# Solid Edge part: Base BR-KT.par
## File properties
Last saved by: nakano
Revision: 76
Density: 1011.76138724735 kg/m^3
Accuracy: 0.990
Material: AL5D plastic
Face Style: Black (dull)
Fill Style: Normal
Virtual Style: Normal
Grouping: Non-metals
LibraryName: Materials-GOST
Coef. of Thermal Exp: 0.0
Thermal Conductivity: 0.0
Specific Heat: 0.0
Modulus of Elasticity: 0.0
Poisson's Ratio: 0.33
Yield Stress: 0.0
Ultimate Stress: 0.0
Elongation: 0.0
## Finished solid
Body 1: solid body, 387 faces, 785 edges, 404 vertices.
  Faces by surface: cylinder 159, plane 89, blend 76, torus 41, sphere 20, cone 2
  Edges by curve: circle 333, line 292, intersection 120, ellipse 40
Bounding box of the edges (mm; curved faces can reach further): 99.568 x 42.316 x 99.568, from (-49.784, 0, -49.784) to (49.784, 42.3164, 49.784).
Cylindrical faces by radius (mm): R0.0254 x70, R0.254 x50, R1.1811 x4, R1.5875 x8, R1.778 x8, R2.1463 x4, R3.175 x5, R3.3655 x4, R4.7625 x5, R9.525 x1
Conical faces (half-angle, radius in mm at the cone's reference point): 4 deg R44.2911 x1, 4 deg R46.8249 x1
Toroidal faces (ring radius, tube radius in mm): R1.524 r0.254 x8, R1.8415 r0.254 x8, R3.2004 r0.0254 x10, R3.429 r0.254 x10, R46.3512 r0.508 x1, R49.8432 r0.254 x4
Spherical faces by radius (mm): R0.0254 x20
Planar faces by outward normal: +x 2, +y 20, +z 1, -x 2, -y 19, -z 1, oblique 44
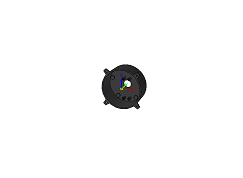
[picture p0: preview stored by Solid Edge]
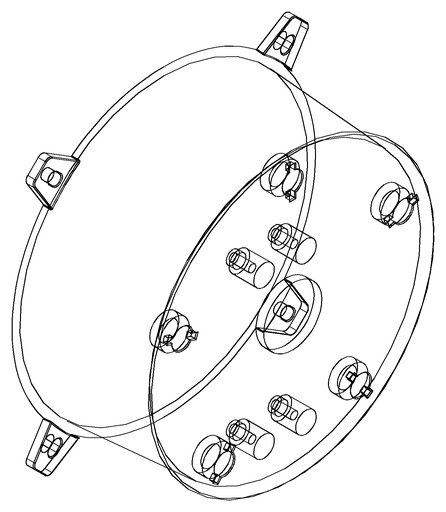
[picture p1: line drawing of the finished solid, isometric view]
